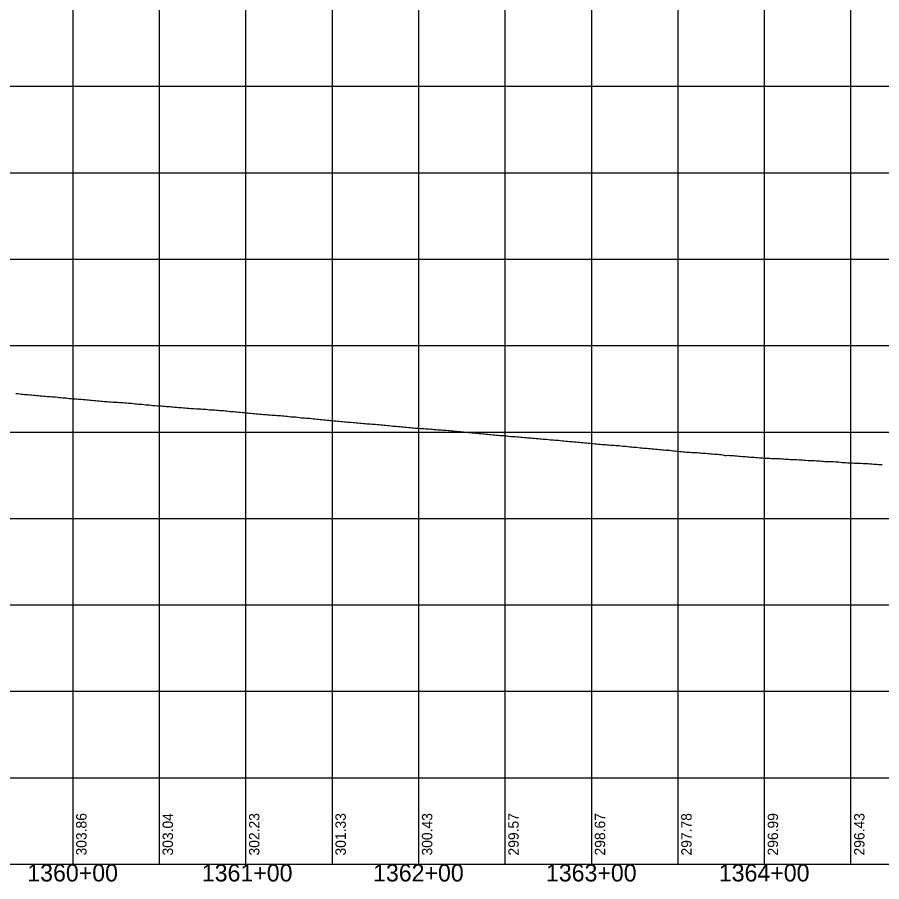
# Model space of a CAD drawing. Extents: x -90830 to 2015517, y -20856 to 836331.
# Drawn here: x 5791 to 6291, y 33641 to 34141 of the extents above; entities that cross this region are included whole.
import ezdxf

# ---------------------------------------------------------------- set-up
doc = ezdxf.new("R2010")
doc.units = 0
for name, color, linetype in [('Level 1', 7, 'Continuous'), ('RD_DDB_Profile_EX', 7, 'Continuous'), ('RD_DDB_StaTX', 7, 'Continuous'), ('RD_DDB_StripGrade', 7, 'Continuous'), ('RD_GPK_Profile_Cell', 7, 'Continuous')]:
    doc.layers.add(name, color=color, linetype=linetype)

msp = doc.modelspace()

# ---------------------------------------------------------------- linework, layer by layer
at = {"layer": 'Level 1'}
for p, q in [((5823.46, 34151.28), (5823.46, 33651.28)), ((5873.46, 34151.28), (5873.46, 33651.28)), ((5923.46, 34151.28), (5923.46, 33651.28)), ((5973.46, 34151.28), (5973.46, 33651.28)), ((6023.46, 34151.28), (6023.46, 33651.28)), ((6073.46, 34151.28), (6073.46, 33651.28)), ((6123.46, 34151.28), (6123.46, 33651.28)), ((6173.46, 34151.28), (6173.46, 33651.28)), ((6223.46, 34151.28), (6223.46, 33651.28)), ((6273.46, 34151.28), (6273.46, 33651.28)), ((4823.46, 34101.28), (6423.46, 34101.28)), ((4823.46, 34051.28), (6423.46, 34051.28)), ((4823.46, 34001.28), (6423.46, 34001.28)), ((4823.46, 33951.28), (6423.46, 33951.28)), ((4823.46, 33901.28), (6423.46, 33901.28)), ((4823.46, 33851.28), (6423.46, 33851.28)), ((4823.46, 33801.28), (6423.46, 33801.28)), ((4823.46, 33751.28), (6423.46, 33751.28)), ((4823.46, 33701.28), (6423.46, 33701.28)), ((4823.46, 33651.28), (6423.46, 33651.28))]:
    msp.add_line(p, q, dxfattribs=at)
at = {"layer": 'RD_DDB_Profile_EX'}
for points in [[(5790.61, 33923.6), (5791.61, 33923.47), (5792.61, 33923.27), (5793.61, 33923.21), (5794.61, 33923.11), (5795.61, 33923.02), (5796.61, 33922.97), (5797.61, 33922.89), (5798.61, 33922.77), (5799.61, 33922.72), (5800.61, 33922.65), (5801.61, 33922.54), (5802.61, 33922.41), (5803.61, 33922.35), (5804.61, 33922.26), (5805.61, 33922.19), (5806.61, 33922.09), (5807.61, 33921.98), (5808.61, 33921.88), (5809.61, 33921.79), (5810.61, 33921.73), (5811.61, 33921.68), (5812.61, 33921.62), (5813.61, 33921.55), (5814.61, 33921.39), (5815.61, 33921.25), (5816.61, 33921.16), (5817.61, 33921.11), (5818.61, 33921.05), (5819.61, 33920.95), (5820.61, 33920.81), (5821.61, 33920.73), (5822.61, 33920.66), (5823.61, 33920.54), (5824.61, 33920.48), (5825.61, 33920.39), (5826.61, 33920.34), (5827.61, 33920.26), (5828.61, 33920.2), (5829.61, 33920.1), (5830.61, 33920), (5831.61, 33919.91), (5832.61, 33919.84), (5833.61, 33919.72), (5834.61, 33919.66), (5835.61, 33919.56), (5836.61, 33919.47), (5837.61, 33919.37), (5838.61, 33919.27), (5839.61, 33919.17), (5840.61, 33919.08), (5841.61, 33919.02), (5842.61, 33918.93), (5843.61, 33918.87), (5844.61, 33918.77), (5845.61, 33918.71), (5846.61, 33918.62), (5847.61, 33918.57), (5848.61, 33918.54), (5849.61, 33918.51), (5850.61, 33918.4), (5851.61, 33918.28), (5852.61, 33918.26), (5853.61, 33918.16), (5854.61, 33918.08), (5855.61, 33918.04), (5856.61, 33918.01), (5857.61, 33917.88), (5858.61, 33917.74), (5859.61, 33917.67), (5860.61, 33917.54), (5861.61, 33917.46), (5862.61, 33917.38), (5863.61, 33917.32), (5864.61, 33917.21), (5865.61, 33917.07), (5866.61, 33917.02), (5867.61, 33916.95), (5868.61, 33916.84), (5869.61, 33916.7), (5870.61, 33916.65), (5871.61, 33916.59), (5872.61, 33916.5), (5873.61, 33916.45), (5874.61, 33916.42), (5875.61, 33916.31), (5876.61, 33916.21), (5877.61, 33916.11), (5878.61, 33916.01), (5879.61, 33915.96), (5880.61, 33915.89), (5881.61, 33915.76), (5882.61, 33915.68), (5883.61, 33915.62), (5884.61, 33915.54)], [(5884.61, 33915.54), (5885.61, 33915.5), (5886.61, 33915.44), (5887.61, 33915.34), (5888.61, 33915.25), (5889.61, 33915.16), (5890.61, 33915.09), (5891.61, 33914.96), (5892.61, 33914.87), (5893.61, 33914.82), (5894.61, 33914.77), (5895.61, 33914.68), (5896.61, 33914.64), (5897.61, 33914.62), (5898.61, 33914.52), (5899.61, 33914.44), (5900.61, 33914.41), (5901.61, 33914.27), (5902.61, 33914.19), (5903.61, 33914.13), (5904.61, 33914.05), (5905.61, 33914.03), (5906.61, 33913.94), (5907.61, 33913.89), (5908.61, 33913.81), (5909.61, 33913.69), (5910.61, 33913.65), (5911.61, 33913.61), (5912.61, 33913.46), (5913.61, 33913.32), (5914.61, 33913.23), (5915.61, 33913.14), (5916.61, 33913.08), (5917.61, 33912.98), (5918.61, 33912.85), (5919.61, 33912.8), (5920.61, 33912.73), (5921.61, 33912.59), (5922.61, 33912.49), (5923.61, 33912.39), (5924.61, 33912.31), (5925.61, 33912.25), (5926.61, 33912.15), (5927.61, 33912.06), (5928.61, 33911.96), (5929.61, 33911.87), (5930.61, 33911.79), (5931.61, 33911.65), (5932.61, 33911.52), (5933.61, 33911.47), (5934.61, 33911.4), (5935.61, 33911.31), (5936.61, 33911.25), (5937.61, 33911.16), (5938.61, 33911.1), (5939.61, 33911.04), (5940.61, 33910.93), (5941.61, 33910.85), (5942.61, 33910.79), (5943.61, 33910.74), (5944.61, 33910.67), (5945.61, 33910.56), (5946.61, 33910.43), (5947.61, 33910.37), (5948.61, 33910.27), (5949.61, 33910.14), (5950.61, 33909.97), (5951.61, 33910), (5952.61, 33909.97), (5953.61, 33909.86), (5954.61, 33909.7), (5955.61, 33909.53), (5956.61, 33909.43), (5957.61, 33909.38), (5958.61, 33909.33), (5959.61, 33909.27), (5960.61, 33909.21), (5961.61, 33909.1), (5962.61, 33908.96), (5963.61, 33908.87), (5964.61, 33908.78), (5965.61, 33908.62), (5966.61, 33908.56), (5967.61, 33908.49), (5968.61, 33908.38), (5969.61, 33908.25), (5970.61, 33908.17), (5971.61, 33908.04), (5972.61, 33907.99), (5973.61, 33907.91), (5974.61, 33907.78), (5975.61, 33907.71), (5976.61, 33907.63), (5977.61, 33907.56), (5978.61, 33907.43), (5979.61, 33907.33), (5980.61, 33907.23), (5981.61, 33907.13), (5982.61, 33907.04), (5983.61, 33906.98), (5984.61, 33906.88)], [(5984.61, 33906.88), (5985.61, 33906.79), (5986.61, 33906.73), (5987.61, 33906.63), (5988.61, 33906.53), (5989.61, 33906.43), (5990.61, 33906.34), (5991.61, 33906.28), (5992.61, 33906.18), (5993.61, 33906.08), (5994.61, 33905.99), (5995.61, 33905.94), (5996.61, 33905.88), (5997.61, 33905.78), (5998.61, 33905.72), (5999.61, 33905.62), (6000.61, 33905.53), (6001.61, 33905.47), (6002.61, 33905.36), (6003.61, 33905.23), (6004.61, 33905.17), (6005.61, 33905.09), (6006.61, 33904.95), (6007.61, 33904.84), (6008.61, 33904.71), (6009.61, 33904.68), (6010.61, 33904.65), (6011.61, 33904.51), (6012.61, 33904.41), (6013.61, 33904.32), (6014.61, 33904.27), (6015.61, 33904.16), (6016.61, 33904.03), (6017.61, 33903.97), (6018.61, 33903.87), (6019.61, 33903.78), (6020.61, 33903.68), (6021.61, 33903.59), (6022.61, 33903.53), (6023.61, 33903.44), (6024.61, 33903.36), (6025.61, 33903.34), (6026.61, 33903.23), (6027.61, 33903.14), (6028.61, 33903.09), (6029.61, 33903.03), (6030.61, 33902.97), (6031.61, 33902.88), (6032.61, 33902.77), (6033.61, 33902.67), (6034.61, 33902.59), (6035.61, 33902.57), (6036.61, 33902.51), (6037.61, 33902.4), (6038.61, 33902.28), (6039.61, 33902.26), (6040.61, 33902.21), (6041.61, 33902.14), (6042.61, 33902), (6043.61, 33901.87), (6044.61, 33901.81), (6045.61, 33901.72), (6046.61, 33901.65), (6047.61, 33901.48), (6048.61, 33901.42), (6049.61, 33901.31), (6050.61, 33901.19), (6051.61, 33901.13), (6052.61, 33901.03), (6053.61, 33900.93), (6054.61, 33900.83), (6055.61, 33900.74), (6056.61, 33900.67), (6057.61, 33900.52), (6058.61, 33900.39), (6059.61, 33900.33), (6060.61, 33900.26), (6061.61, 33900.13), (6062.61, 33900.05), (6063.61, 33900.02), (6064.61, 33899.91), (6065.61, 33899.77), (6066.61, 33899.67), (6067.61, 33899.57), (6068.61, 33899.51), (6069.61, 33899.42), (6070.61, 33899.35), (6071.61, 33899.26), (6072.61, 33899.19), (6073.61, 33899.1), (6074.61, 33899.01), (6075.61, 33898.92), (6076.61, 33898.76), (6077.61, 33898.71), (6078.61, 33898.66), (6079.61, 33898.6), (6080.61, 33898.5), (6081.61, 33898.4), (6082.61, 33898.3), (6083.61, 33898.21), (6084.61, 33898.15)], [(6084.61, 33898.15), (6085.61, 33898.08), (6086.61, 33897.95), (6087.61, 33897.9), (6088.61, 33897.83), (6089.61, 33897.73), (6090.61, 33897.64), (6091.61, 33897.59), (6092.61, 33897.51), (6093.61, 33897.38), (6094.61, 33897.31), (6095.61, 33897.21), (6096.61, 33897.12), (6097.61, 33897.06), (6098.61, 33896.99), (6099.61, 33896.84), (6100.61, 33896.75), (6101.61, 33896.69), (6102.61, 33896.64), (6103.61, 33896.57), (6104.61, 33896.46), (6105.61, 33896.32), (6106.61, 33896.24), (6107.61, 33896.18), (6108.61, 33896.07), (6109.61, 33895.9), (6110.61, 33895.86), (6111.61, 33895.81), (6112.61, 33895.74), (6113.61, 33895.6), (6114.61, 33895.51), (6115.61, 33895.41), (6116.61, 33895.31), (6117.61, 33895.22), (6118.61, 33895.16), (6119.61, 33895.05), (6120.61, 33894.92), (6121.61, 33894.86), (6122.61, 33894.76), (6123.61, 33894.63), (6124.61, 33894.57), (6125.61, 33894.48), (6126.61, 33894.4), (6127.61, 33894.23), (6128.61, 33894.18), (6129.61, 33894.11), (6130.61, 33894.03), (6131.61, 33893.96), (6132.61, 33893.87), (6133.61, 33893.81), (6134.61, 33893.71), (6135.61, 33893.62), (6136.61, 33893.57), (6137.61, 33893.5), (6138.61, 33893.42), (6139.61, 33893.39), (6140.61, 33893.25), (6141.61, 33893.16), (6142.61, 33893.09), (6143.61, 33893), (6144.61, 33892.93), (6145.61, 33892.77), (6146.61, 33892.62), (6147.61, 33892.6), (6148.61, 33892.5), (6149.61, 33892.42), (6150.61, 33892.35), (6151.61, 33892.21), (6152.61, 33892.07), (6153.61, 33891.99), (6154.61, 33891.97), (6155.61, 33891.87), (6156.61, 33891.74), (6157.61, 33891.69), (6158.61, 33891.58), (6159.61, 33891.45), (6160.61, 33891.39), (6161.61, 33891.3), (6162.61, 33891.25), (6163.61, 33891.19), (6164.61, 33891.05), (6165.61, 33890.94), (6166.61, 33890.81), (6167.61, 33890.76), (6168.61, 33890.7), (6169.61, 33890.59), (6170.61, 33890.44), (6171.61, 33890.31), (6172.61, 33890.26), (6173.61, 33890.19), (6174.61, 33890.06), (6175.61, 33889.99), (6176.61, 33889.84), (6177.61, 33889.74), (6178.61, 33889.66), (6179.61, 33889.61), (6180.61, 33889.59), (6181.61, 33889.49), (6182.61, 33889.42), (6183.61, 33889.43), (6184.61, 33889.33)], [(6184.61, 33889.33), (6185.61, 33889.28), (6186.61, 33889.21), (6187.61, 33889.11), (6188.61, 33889.03), (6189.61, 33888.95), (6190.61, 33888.88), (6191.61, 33888.81), (6192.61, 33888.68), (6193.61, 33888.58), (6194.61, 33888.5), (6195.61, 33888.49), (6196.61, 33888.42), (6197.61, 33888.28), (6198.61, 33888.19), (6199.61, 33888.08), (6200.61, 33887.77), (6201.61, 33887.78), (6202.61, 33887.84), (6203.61, 33887.75), (6204.61, 33887.7), (6205.61, 33887.59), (6206.61, 33887.46), (6207.61, 33887.4), (6208.61, 33887.35), (6209.61, 33887.29), (6210.61, 33887.19), (6211.61, 33887.11), (6212.61, 33887.07), (6213.61, 33886.93), (6214.61, 33886.84), (6215.61, 33886.79), (6216.61, 33886.73), (6217.61, 33886.64), (6218.61, 33886.58), (6219.61, 33886.52), (6220.61, 33886.42), (6221.61, 33886.36), (6222.61, 33886.27), (6223.61, 33886.22), (6224.61, 33886.21), (6225.61, 33886.15), (6226.61, 33886.07), (6227.61, 33886.03), (6228.61, 33886.03), (6229.61, 33886.04), (6230.61, 33886.02), (6231.61, 33885.93), (6232.61, 33885.87), (6233.61, 33885.78), (6234.61, 33885.72), (6235.61, 33885.64), (6236.61, 33885.59), (6237.61, 33885.53), (6238.61, 33885.44), (6239.61, 33885.39), (6240.61, 33885.35), (6241.61, 33885.31), (6242.61, 33885.28), (6243.61, 33885.19), (6244.61, 33885.15), (6245.61, 33885.13), (6246.61, 33885.04), (6247.61, 33884.98), (6248.61, 33884.89), (6249.61, 33884.83), (6250.61, 33884.75), (6251.61, 33884.75), (6252.61, 33884.72), (6253.61, 33884.64), (6254.61, 33884.63), (6255.61, 33884.56), (6256.61, 33884.47), (6257.61, 33884.4), (6258.61, 33884.31), (6259.61, 33884.26), (6260.61, 33884.22), (6261.61, 33884.21), (6262.61, 33884.2), (6263.61, 33884.13), (6264.61, 33884.05), (6265.61, 33884.04), (6266.61, 33883.93), (6267.61, 33883.79), (6268.61, 33883.67), (6269.61, 33883.62), (6270.61, 33883.57), (6271.61, 33883.54), (6272.61, 33883.51), (6273.61, 33883.4), (6274.61, 33883.39), (6275.61, 33883.34), (6276.61, 33883.3), (6277.61, 33883.24), (6278.61, 33883.16), (6279.61, 33883.16), (6280.61, 33883.1), (6281.61, 33883.06), (6282.61, 33883.02), (6283.61, 33883.01), (6284.61, 33882.96)], [(6284.61, 33882.96), (6285.61, 33882.89), (6286.61, 33882.75), (6287.61, 33882.66), (6288.61, 33882.61), (6289.61, 33882.56), (6290.61, 33882.51), (6291.61, 33882.47)]]:
    msp.add_lwpolyline(points, dxfattribs=at)
at = {"layer": 'RD_GPK_Profile_Cell'}
msp.add_line((4884.61, 33651.28), (7384.61, 33651.28), dxfattribs=at)

# ---------------------------------------------------------------- texts
at = {"layer": 'RD_DDB_StaTX'}
for s, p in [('1360+00', (5797.21, 33641.28)), ('1361+00', (5898.17, 33641.28)), ('1362+00', (5997.21, 33641.28)), ('1363+00', (6097.21, 33641.28)), ('1364+00', (6197.21, 33641.28))]:
    msp.add_text(s, height=10, dxfattribs=at).set_placement(p)
at = {"layer": 'RD_DDB_StripGrade'}
for s, p in [('303.86', (5831.46, 33656.28)), ('303.04', (5881.46, 33656.28)), ('302.23', (5931.46, 33656.28)), ('301.33', (5981.46, 33656.28)), ('300.43', (6031.46, 33656.28)), ('299.57', (6081.46, 33656.28)), ('298.67', (6131.46, 33656.28)), ('297.78', (6181.46, 33656.28)), ('296.99', (6231.46, 33656.28)), ('296.43', (6281.46, 33656.28))]:
    msp.add_text(s, height=6, rotation=90, dxfattribs=at).set_placement(p)

doc.saveas('drawing.dxf')
